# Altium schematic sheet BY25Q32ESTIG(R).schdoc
size 127 x 101 mm
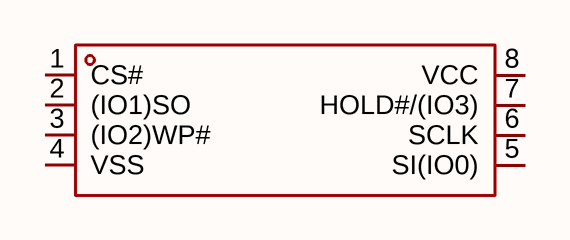
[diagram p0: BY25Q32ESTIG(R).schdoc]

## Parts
U?  by25q32estig(r)  [SOP-8_L4.9-W3.9-P1.27-LS6.0-BL]  (value not drawn)

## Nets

Not connected (* = marked no-connect by the designer): U? 1(CS#) 2((IO1)SO) 3((IO2)WP#) 4(VSS) 5(SI(IO0)) 6(SCLK) 7(HOLD#/(IO3)) 8(VCC)

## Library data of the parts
U? = by25q32estig(r): Manufacturer: BOYAMICRO(博雅); AddInBom: yes; ModelId: 75c24a7891ee4dd6bdac16a7163ff87e; ModelName: SOP-8_L4.9-W3.9-P1.27-LS6.0-BL-1; ModelTransform: 192.913,236.22,0,0,0,0,-0.393,2.749,0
